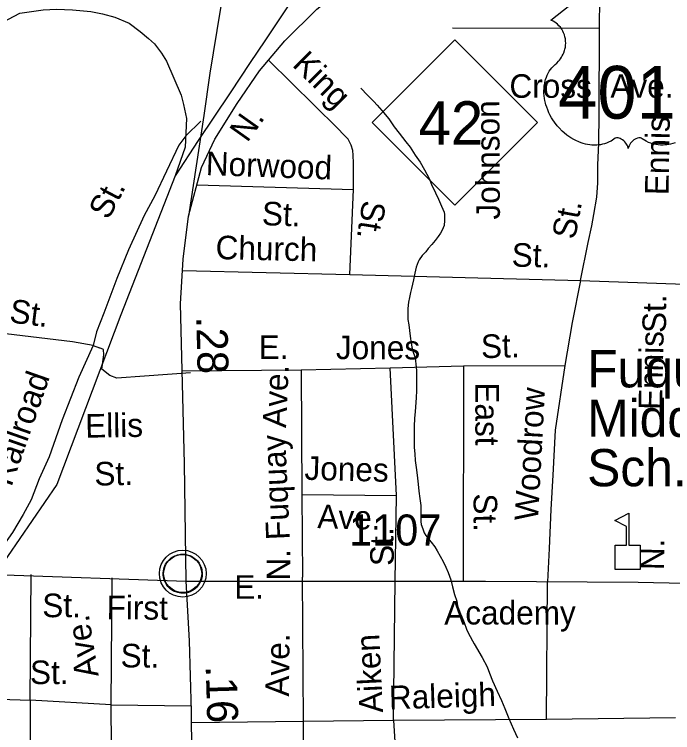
# Model space of a CAD drawing. Extents: x 2001466 to 2224147, y 644118 to 847247.
# Drawn here: x 2058818 to 2061470, y 667039 to 669932 of the extents above; entities that cross this region are included whole.
import ezdxf

# ---------------------------------------------------------------- set-up
doc = ezdxf.new("R2010")
doc.units = 0
for name, color, linetype in [('Exist Civil Demographics Community CELL', 7, 'Continuous'), ('Exist Cultural Educational Facility Elementary CELL', 7, 'Continuous'), ('Exist Cultural Educational Facility Elementary Label', 7, 'Continuous'), ('Exist Hydrographic Misc Water Feature', 7, 'Continuous'), ('Exist Railroad Mainline', 7, 'Continuous'), ('Exist Road Non-System Type 51', 7, 'Continuous'), ('Exist Road Non-System Type 51 Label', 7, 'Continuous'), ('Exist Road Primary NC Attributed', 7, 'Continuous'), ('Exist Road Primary NC Label', 7, 'Continuous'), ('Exist Road Primary NC Shield CELL', 7, 'Continuous'), ('Exist Road Primary NC Shield Number Label', 7, 'Continuous'), ('Exist Road Primary US Attributed', 7, 'Continuous'), ('Exist Road Primary US Label', 7, 'Continuous'), ('Exist Road Primary US Mileage Hundredths English Label', 7, 'Continuous'), ('Exist Road Primary US Shield CELL', 7, 'Continuous'), ('Exist Road Primary US Shield Number Label', 7, 'Continuous'), ('Exist Road Secondary Type 51 Attributed', 7, 'Continuous'), ('Exist Road Secondary Type 51 Label', 7, 'Continuous'), ('Exist Road Secondary Type 51 Number Label', 7, 'Continuous')]:
    doc.layers.add(name, color=color, linetype=linetype)

msp = doc.modelspace()

# ---------------------------------------------------------------- linework, layer by layer
at = {"layer": 'Exist Civil Demographics Community CELL'}
msp.add_lwpolyline([(2059419.2, 667692.1), (2059420.2, 667697.7), (2059421.9, 667704.3), (2059424.8, 667711.5), (2059427.8, 667717.2), (2059431.1, 667723), (2059434.9, 667728.1), (2059438.8, 667732.5), (2059443.4, 667737.1), (2059449, 667741.7), (2059454.4, 667745.3), (2059459.3, 667748.2), (2059464.3, 667750.6), (2059469.8, 667752.9), (2059475.4, 667754.8), (2059479.7, 667755.9), (2059484.6, 667756.6), (2059488.7, 667757.4), (2059495.1, 667757.6), (2059499.5, 667757.5), (2059505.2, 667757.3), (2059510.1, 667756.5), (2059515, 667755.5), (2059520, 667754.1), (2059525.2, 667752.2), (2059531.8, 667749.3), (2059538.1, 667745.8), (2059543.1, 667742.2), (2059548.3, 667738.2), (2059551.6, 667735.1), (2059555.7, 667730.7), (2059559.6, 667726), (2059562.7, 667721.4), (2059565.8, 667716.4), (2059568.3, 667711.2), (2059570.3, 667706.2), (2059571.9, 667701.2), (2059573.1, 667696.6), (2059574.2, 667690.6), (2059574.9, 667685.9), (2059575.1, 667679.9), (2059574.9, 667674.1), (2059574.4, 667668.4), (2059573.4, 667662.9), (2059571.8, 667656.8), (2059569.9, 667650.9), (2059567.6, 667645.9), (2059564.5, 667639.9), (2059561.2, 667634.5), (2059557.7, 667629.8), (2059553.5, 667625.1), (2059548.2, 667620.1), (2059543.2, 667616), (2059538.2, 667612.6), (2059533.8, 667610.1), (2059527, 667606.8), (2059519.9, 667604.1), (2059513.9, 667602.7), (2059507.3, 667601.3), (2059502.9, 667600.9), (2059498.4, 667600.6), (2059492.8, 667600.6), (2059488.6, 667601), (2059482.9, 667601.8), (2059477, 667603.1), (2059472.4, 667604.4), (2059467.2, 667606.3), (2059462.6, 667608.2), (2059458.7, 667610.5), (2059451.9, 667614.6), (2059446.3, 667618.8), (2059441.4, 667623.3), (2059437, 667628.2), (2059433.8, 667632.1), (2059430.8, 667636.3), (2059426.7, 667643.4), (2059425, 667647), (2059423.3, 667651), (2059420.7, 667659.2), (2059419.2, 667666.2), (2059418.5, 667671.4), (2059418.1, 667677.7), (2059418.1, 667682.4), (2059418.6, 667688.9)], close=True, dxfattribs=at)
for centre, radius in [((2059496.8, 667679.7), 94.3), ((2059496.5, 667680), 76.7)]:
    msp.add_circle(centre, radius, dxfattribs=at)
at = {"layer": 'Exist Cultural Educational Facility Elementary CELL'}
msp.add_lwpolyline([(2061238.4, 667696.7), (2061238.4, 667794.6), (2061284.5, 667794.6), (2061284.5, 667869.7), (2061237.4, 667893.9), (2061294.1, 667923.1), (2061294.1, 667794.6), (2061340.1, 667794.6), (2061340.1, 667696.7)], close=True, dxfattribs=at)
at = {"layer": 'Exist Hydrographic Misc Water Feature'}
for points in [[(2060214.7, 669634.9), (2060240.5, 669607), (2060266.8, 669581), (2060280.7, 669567), (2060298.7, 669545.1), (2060326.8, 669511.1), (2060348.8, 669479.2), (2060368.9, 669453.2), (2060394.9, 669419.3), (2060413, 669397.3), (2060433.1, 669365.4), (2060453.1, 669337.4), (2060471, 669305.5), (2060489.2, 669271.5), (2060499.3, 669247.6), (2060515.3, 669213.6), (2060527.4, 669187.6), (2060539.3, 669159.6), (2060549.5, 669135.6), (2060551.4, 669125.7), (2060551.4, 669117.7), (2060551.4, 669101.7), (2060549.5, 669081.7), (2060541.5, 669063.6), (2060535.6, 669051.6), (2060525.5, 669037.6), (2060513.6, 669021.6), (2060499.7, 669005.5), (2060485.7, 668989.5), (2060475.7, 668975.6), (2060461.8, 668961.5), (2060449.9, 668943.5), (2060445.8, 668935.5), (2060437.8, 668913.5), (2060432, 668889.5), (2060425.9, 668863.5), (2060422, 668845.5), (2060417.9, 668827.5), (2060414, 668811.5), (2060410.1, 668791.4), (2060406, 668773.4), (2060404.1, 668747.4), (2060404.1, 668721.5), (2060404.1, 668703.5), (2060408.2, 668681.5), (2060410.3, 668659.5), (2060414.4, 668625.5), (2060416.4, 668609.5), (2060420.3, 668591.5), (2060426.5, 668567.6), (2060432.6, 668549.6), (2060436.5, 668523.6), (2060438.6, 668497.5), (2060438.6, 668471.5), (2060438.6, 668441.5), (2060438.8, 668415.6), (2060436.7, 668389.6), (2060432.8, 668331.6), (2060431, 668305.6), (2060428.9, 668271.6), (2060428.9, 668237.6), (2060428.9, 668215.6), (2060429.2, 668187.6), (2060431.2, 668161.6), (2060433.3, 668135.6), (2060437.4, 668107.6), (2060441.5, 668075.7), (2060445.4, 668039.6), (2060447.4, 668011.7), (2060451.5, 667981.7), (2060455.6, 667953.7), (2060455.6, 667921.7), (2060455.6, 667909.7), (2060455.6, 667889.8), (2060457.7, 667877.8), (2060463.8, 667859.7), (2060469.8, 667843.7), (2060475.7, 667833.7), (2060483.7, 667821.8), (2060497.8, 667805.8), (2060512, 667787.8), (2060521.8, 667771.8), (2060533.9, 667749.9), (2060545.8, 667727.9), (2060556.1, 667705.9), (2060566.1, 667684), (2060576.2, 667654), (2060584.2, 667626), (2060592.2, 667596.1), (2060600.4, 667568), (2060604.3, 667550), (2060612.3, 667526), (2060618.4, 667512.1), (2060630.3, 667482.1), (2060640.4, 667456.2), (2060648.6, 667438.2), (2060654.5, 667426.2), (2060664.6, 667408.2), (2060670.5, 667396.2), (2060702.7, 667342.3)], [(2060702.7, 667342.3), (2060722.6, 667304.3), (2060732.8, 667278.4), (2060744.7, 667248.3), (2060763, 667206.4), (2060780.8, 667168.5), (2060795, 667136.5), (2060811, 667096.6), (2060829.2, 667052.6), (2060845.2, 667018.6)]]:
    msp.add_lwpolyline(points, dxfattribs=at)
at = {"layer": 'Exist Railroad Mainline'}
for points in [[(2060579.4, 670640.8), (2060483.4, 670595.2), (2060418.4, 670557.8), (2060351.4, 670508.7), (2060293.3, 670461.7), (2060231.9, 670398.7), (2060169.9, 670329.9), (2060124, 670266.8), (2060083.7, 670207), (2060019.6, 670110.4), (2059969.8, 670041.3), (2059920.9, 669966.6), (2059826.9, 669825.2), (2059767.8, 669738), (2059687.5, 669616.1), (2059558.3, 669424.8), (2059466.8, 669281.5)], [(2058840.6, 669936.5), (2058934.9, 669950.9), (2058987.6, 669953.9), (2059053.3, 669950.9), (2059127, 669944.4), (2059173.2, 669935.1), (2059223.3, 669921.1), (2059281.2, 669897.1), (2059325.3, 669863.2), (2059359.4, 669835.1), (2059383.3, 669813.2), (2059410.9, 669775.9), (2059431.5, 669743.9), (2059489.9, 669606.6), (2059499.3, 669568.8), (2059512.3, 669513.2), (2059506.7, 669398), (2059466.8, 669281.5)], [(2046464.5, 663426.2), (2046524.6, 663459.1), (2048551.7, 664535.4), (2049194.6, 664876.7), (2049524.4, 665051.8), (2049557.2, 665070.3), (2052622.8, 666680.7), (2055671.2, 668278.9), (2056997.6, 668963.3), (2058840.6, 669936.5)], [(2059466.8, 669281.5), (2059247, 668722.4), (2058989.3, 668038.2), (2058739.5, 667675.8), (2058666.3, 667594.6), (2058590.1, 667522), (2058509.7, 667458.7), (2058422.8, 667398.4), (2058302, 667328.4), (2058175.7, 667270.8), (2058052.8, 667223.4), (2058004.9, 667201.4), (2057789.6, 667118.3), (2057420.7, 666969.3), (2057032.5, 666817.2), (2056669.9, 666670.1), (2056479.2, 666595.3), (2056311, 666527.9), (2056095.5, 666440.8), (2055989.5, 666391.7), (2055913.4, 666350.9), (2055836.9, 666300.6), (2055727.1, 666216.2), (2055641.1, 666137.7)]]:
    msp.add_lwpolyline(points, dxfattribs=at)
at = {"layer": 'Exist Road Non-System Type 51'}
for p, q in [((2061176.3, 669876.9), (2061178, 670253.3)), ((2060583.8, 669878.5), (2061176.3, 669876.9)), ((2059569.4, 669502.4), (2059508.9, 669443.5)), ((2059553.2, 669246.1), (2060185, 669227.1)), ((2060169.6, 668884.9), (2060185, 669227.1)), ((2059495.2, 668900.5), (2060169.6, 668884.9)), ((2060169.6, 668884.9), (2061099.1, 668860)), ((2061099.1, 668860), (2061519.8, 668845.2)), ((2059136, 668598.9), (2059161.9, 668589.4)), ((2059973.3, 668499.9), (2060332.8, 668507.9)), ((2060332.8, 668507.9), (2060628.4, 668516)), ((2060358.2, 667994.2), (2060332.8, 668507.9)), ((2060628.4, 668516), (2060626.6, 667648.9)), ((2060628.4, 668516), (2061036, 668517.3)), ((2059494, 668496.6), (2059973.3, 668499.9)), ((2059973.3, 668499.9), (2059976, 667997.9)), ((2059976, 667997.9), (2060358.2, 667994.2)), ((2059976, 667997.9), (2059978.8, 667664.7)), ((2060352.8, 667648.9), (2060358.2, 667994.2)), ((2059983.8, 667084.7), (2059978.8, 667664.7))]:
    msp.add_line(p, q, dxfattribs=at)
for points in [[(2061099.1, 668860), (2061130.2, 669013.4), (2061144.3, 669080.8), (2061153.6, 669126.2), (2061165.7, 669195.8), (2061169.7, 669253.3), (2061169.7, 669325.5), (2061173.7, 669415.1), (2061175, 669529), (2061176.3, 669876.9)], [(2060185, 669227.1), (2060185, 669332.7), (2060183.7, 669364.8), (2060182.3, 669383.5), (2060175.7, 669404.9), (2060162.7, 669429), (2060147, 669445.3), (2060119.6, 669473.9), (2059842.7, 669747.8)], [(2059508.9, 669443.5), (2059480.5, 669405.4), (2059431.3, 669300.8), (2059384.6, 669201.2), (2059342, 669122.7), (2059278.5, 668983.2), (2059231.8, 668868.6), (2059178.9, 668729.1), (2059149.7, 668653.1), (2059136, 668598.9)], [(2061099.1, 668860), (2061065.7, 668690.7), (2061036, 668517.3)], [(2059136, 668598.9), (2059053.2, 668613.9), (2058716.1, 668653.2)], [(2059136, 668598.9), (2059078.5, 668470.9), (2059011.3, 668298.6), (2058958.7, 668150.5), (2058918.9, 668060.8), (2058886.1, 667976.2), (2058853.4, 667917.1), (2058810.5, 667845), (2058771.4, 667789.8), (2058696, 667676.5)], [(2059527.9, 668488.1), (2059342.8, 668474.8), (2059231.8, 668466.8), (2059202.4, 668477.5), (2059170.8, 668503.6), (2059178.9, 668560.9), (2059177.1, 668581.8), (2059161.9, 668589.4)], [(2061036, 668517.3), (2060996.9, 668258.1), (2060987.1, 668076.3), (2060979.1, 667938), (2060972.4, 667780.3), (2060966.2, 667647.1)], [(2058881.5, 667170.5), (2058886.2, 667676.3)], [(2059208.9, 667150.5), (2059212.3, 667662.9)], [(2060345.9, 667088.7), (2060352.8, 667648.9)], [(2060962, 667093), (2060966.2, 667647.1)], [(2058269.2, 667190.6), (2058881.5, 667170.5)], [(2058881.5, 667170.5), (2058880.2, 666820.2), (2059211.6, 666816.2)], [(2059208.9, 667150.5), (2058881.5, 667170.5)], [(2059211.6, 666816.2), (2059208.9, 667150.5)], [(2059208.9, 667150.5), (2059531.3, 667146.5)], [(2059983.8, 667084.7), (2060345.9, 667088.7)], [(2060345.9, 667088.7), (2060962, 667093)], [(2060345.9, 667088.7), (2060364.5, 666783.9)], [(2060962, 667093), (2061481.3, 667099.6)], [(2059532.4, 667080.4), (2059983.8, 667084.7)], [(2059982.4, 666792.3), (2059983.8, 667084.7)]]:
    msp.add_lwpolyline(points, dxfattribs=at)
at = {"layer": 'Exist Road Primary NC Attributed'}
msp.add_lwpolyline([(2057313.3, 667698.2), (2057695.8, 667700.3), (2058382.3, 667681.5), (2058739.5, 667675.8), (2059511, 667649)], dxfattribs=at)
at = {"layer": 'Exist Road Primary NC Shield CELL'}
msp.add_lwpolyline([(2060259.9, 669496.9), (2060592.9, 669829.9), (2060925.9, 669496.9), (2060592.9, 669163.9)], close=True, dxfattribs=at)
at = {"layer": 'Exist Road Primary US Attributed'}
for points in [[(2059519.4, 669119.4), (2059571.7, 669315.2), (2059625.6, 669429.3), (2059715.6, 669572.8), (2059806.6, 669704.8), (2059907.6, 669825.2), (2060037.4, 669953), (2060153.6, 670044.1), (2060298, 670136.2), (2060428.8, 670192.8), (2060572.7, 670229.4), (2060696.2, 670244.1), (2060923.3, 670249.3), (2061192.8, 670253.5), (2061442, 670250.3)], [(2059511, 667649), (2059503.2, 668123.4), (2059487.5, 668766.4), (2059497.9, 668946.6), (2059519.4, 669119.4)], [(2059535.1, 666795.5), (2059531.9, 667124.3), (2059523.6, 667409.2), (2059511, 667649)]]:
    msp.add_lwpolyline(points, dxfattribs=at)
at = {"layer": 'Exist Road Primary US Shield CELL'}
msp.add_lwpolyline([(2061481, 669415), (2061462, 669409.8), (2061455.1, 669408.3), (2061446.9, 669407.1), (2061439.2, 669406.3), (2061431.8, 669405.9), (2061421.8, 669405.9), (2061411.8, 669406.6), (2061402.4, 669408), (2061392.6, 669410.1), (2061382.3, 669413.1), (2061373, 669416.8), (2061363.6, 669421.4), (2061347.7, 669431.4), (2061343.1, 669433.8), (2061340.5, 669434.5), (2061334.4, 669434.8), (2061328.6, 669433.6), (2061322.7, 669431.3), (2061319.1, 669429.4), (2061314.4, 669426.3), (2061310.7, 669423.4), (2061306.3, 669419.2), (2061303.3, 669415.7), (2061301, 669413), (2061296.5, 669405.9), (2061294.9, 669402.5), (2061293.2, 669398.2), (2061291.8, 669391.8), (2061289.7, 669399.9), (2061287.4, 669405.2), (2061284.6, 669409.8), (2061281.8, 669413.8), (2061277.3, 669419), (2061273.3, 669422.8), (2061268.4, 669426.8), (2061263.3, 669429.9), (2061259.1, 669432), (2061255.3, 669433.5), (2061250.7, 669434.6), (2061246.9, 669434.9), (2061243.8, 669434.8), (2061239.5, 669433.9), (2061233.7, 669429.7), (2061228.2, 669425.9), (2061222.2, 669422.1), (2061215, 669418.3), (2061209.8, 669415.9), (2061203.6, 669413.5), (2061196.3, 669411.1), (2061188.4, 669409), (2061180.2, 669407.4), (2061173.1, 669406.3), (2061165.4, 669405.6), (2061158.5, 669405.4), (2061151.3, 669405.4), (2061144.6, 669406), (2061136.7, 669406.6), (2061127, 669408.1), (2061119, 669409.9), (2061110.5, 669412.2), (2061101.7, 669414.9), (2061092.4, 669418.5), (2061080.7, 669423.6), (2061072.6, 669427.8), (2061059.7, 669435.1), (2061044.7, 669445.6), (2061033.3, 669454.7), (2061025, 669462.3), (2061012.8, 669474.7), (2061005.6, 669482.9), (2060994.3, 669497.4), (2060987.1, 669508), (2060982.4, 669515.8), (2060975.6, 669528.2), (2060971.9, 669536), (2060967, 669547.4), (2060963.2, 669557.9), (2060960, 669567.7), (2060958.3, 669574), (2060955.8, 669585.1), (2060954.3, 669592.9), (2060952.9, 669603.6), (2060952.1, 669614.9), (2060952, 669625.3), (2060952.2, 669634), (2060953.2, 669644.1), (2060954.9, 669654.8), (2060957, 669664), (2060958.8, 669670.6), (2060961.6, 669678.7), (2060965.2, 669687.6), (2060969.4, 669696.1), (2060973.5, 669703.1), (2060978.6, 669710.7), (2060983.6, 669717.2), (2060990.2, 669724.3), (2060997, 669730.9), (2061003.3, 669736), (2061010.7, 669743.3), (2061014.6, 669747.7), (2061019.2, 669753.8), (2061023, 669759.5), (2061025.9, 669764.6), (2061029.8, 669772.1), (2061032.2, 669777.8), (2061035.2, 669786.4), (2061036.6, 669792.5), (2061038.2, 669800.3), (2061039.1, 669807.7), (2061039.5, 669816.9), (2061039.3, 669824.5), (2061038.3, 669833.4), (2061036.6, 669841.9), (2061034.6, 669849.3), (2061031.4, 669857.9), (2061028.5, 669864.1), (2061023.6, 669872.5), (2061018.1, 669880.3), (2061012.4, 669886.7), (2061006.8, 669892.4), (2061001.3, 669896.7), (2060996.1, 669900.4), (2060989.6, 669904.4), (2060983.2, 669907.5), (2060979.3, 669909.1), (2061107.9, 670011.5)], dxfattribs=at)
at = {"layer": 'Exist Road Secondary Type 51 Attributed'}
for points in [[(2059731.4, 670393.6), (2059673.3, 670093.1), (2059647.9, 669948.9), (2059605.7, 669695.9)], [(2059605.7, 669695.9), (2059581.5, 669525)], [(2059581.5, 669525), (2059519.4, 669119.4)], [(2059511, 667649), (2060002.9, 667648.9), (2060717, 667648.9), (2061331.8, 667644.6), (2061768.3, 667636.2), (2062000.5, 667646.7), (2062109.2, 667643.6), (2062225.3, 667616.1), (2062435.9, 667538), (2062567.9, 667527.4), (2062660.7, 667531.6), (2062803.2, 667571.8), (2062951.5, 667642.5), (2063098.3, 667734.4), (2063179.5, 667759.8), (2063253.4, 667768.2), (2063333.7, 667759.8), (2063539, 667716.5), (2063856.7, 667648.9), (2064013.9, 667620.3), (2064115.4, 667601.2)]]:
    msp.add_lwpolyline(points, dxfattribs=at)

# ---------------------------------------------------------------- texts
at = {"layer": 'Exist Cultural Educational Facility Elementary Label'}
for s, p in [('Fuquay', (2061125.9, 668429.9)), ('Middle', (2061125.9, 668230.7)), ('Sch.', (2061125.9, 668031.4))]:
    msp.add_text(s, height=150, dxfattribs=at).set_placement(p)
at = {"layer": 'Exist Road Non-System Type 51 Label'}
for s, rotation, p in [('King', 315.3149, (2059934.4, 669726.2)), ('Johnson', 90.3346, (2060774.8, 669105.8)), ('Ennis', 89.0042, (2061453.8, 669203.5)), ('Norwood', 357.9358, (2059588.6, 669285.1)), (' St.', 62.2692, (2059180.7, 669069.7)), (' St.', 357.9358, (2059779.4, 669084.7)), (' St.', 261.0441, (2060227.5, 669221.6)), (' St.', 79.372, (2061070.7, 668988.1)), ('Church', 358.6707, (2059628.3, 668946.6)), (' St.', 358.467, (2060785.9, 668917.6)), (' St.', 352.7214, (2058760.6, 668696.5)), (' St.', 89.5108, (2061443.2, 668613.2)), ('Ennis', 88.8339, (2061427.9, 668338.2)), ('E. ', 359.7644, (2059802.5, 668544.7)), ('Jones', 359.7973, (2060113.8, 668543.5)), (' St.', 1.6852, (2060664.3, 668546)), ('Ave.', 87.5196, (2059913, 668265.3)), ('Railroad', 70.7123, (2058806.3, 668026.4)), ('East', 270.0672, (2060675.5, 668449.8)), ('Woodrow', 86.9445, (2060928, 667890.8)), ('Ellis', 0.8886, (2059104.5, 668227.1)), ('Fuquay', 92.5408, (2059928.2, 667817)), ('St.', 0.8886, (2059141.6, 668034.2)), ('Jones', 358.5207, (2059986.5, 668057.8)), (' St.', 270.0672, (2060668.5, 668038)), ('Ave.', 358.5207, (2060038.2, 667862.9)), (' St.', 91.4364, (2060349, 667676.4)), ('N. ', 89.0493, (2061435.5, 667693.2)), ('N. ', 89.8328, (2059929.5, 667651.6)), ('First', 359.4269, (2059189.7, 667496.2)), ('Ave.', 99.2175, (2059158.4, 667268.1)), ('Ave.', 89.4184, (2059924.7, 667184.1)), ('Aiken', 92.8005, (2060303.7, 667120.7)), ('St.', 359.4269, (2059246.2, 667302.2)), ('St.', 359.8848, (2058881.3, 667234.7)), ('Raleigh', 1.8495, (2060329, 667132.6))]:
    msp.add_text(s, height=95, rotation=rotation, dxfattribs=at).set_placement(p)
for s, p in [('Cross', (2060813, 669596.1)), ('Ave.', (2061219.6, 669596.1))]:
    msp.add_text(s, height=95, dxfattribs=at).set_placement(p)
at = {"layer": 'Exist Road Primary NC Label'}
msp.add_text('St.', height=95, dxfattribs=at).set_placement((2058931, 667504))
at = {"layer": 'Exist Road Primary NC Shield Number Label'}
msp.add_text('42', height=175, dxfattribs=at).set_placement((2060447, 669407.2))
at = {"layer": 'Exist Road Primary US Label'}
msp.add_text('N.', height=95, rotation=54.6159, dxfattribs=at).set_placement((2059756.7, 669412.9))
at = {"layer": 'Exist Road Primary US Mileage Hundredths English Label'}
for s, rotation, p in [('.28', 271.3986, (2059551.2, 668714.8)), ('.16', 271.6836, (2059589.1, 667308))]:
    msp.add_text(s, height=125, rotation=rotation, dxfattribs=at).set_placement(p)
at = {"layer": 'Exist Road Primary US Shield Number Label'}
msp.add_text('401', height=212.5, dxfattribs=at).set_placement((2061009.1, 669512.2))
at = {"layer": 'Exist Road Secondary Type 51 Label'}
for s, p in [('E.', (2059704.3, 667578.2)), ('Academy', (2060550.4, 667474.6))]:
    msp.add_text(s, height=95, dxfattribs=at).set_placement(p)
at = {"layer": 'Exist Road Secondary Type 51 Number Label'}
msp.add_text('1107', height=125, dxfattribs=at).set_placement((2060166.7, 667792.8))

doc.saveas('drawing.dxf')
